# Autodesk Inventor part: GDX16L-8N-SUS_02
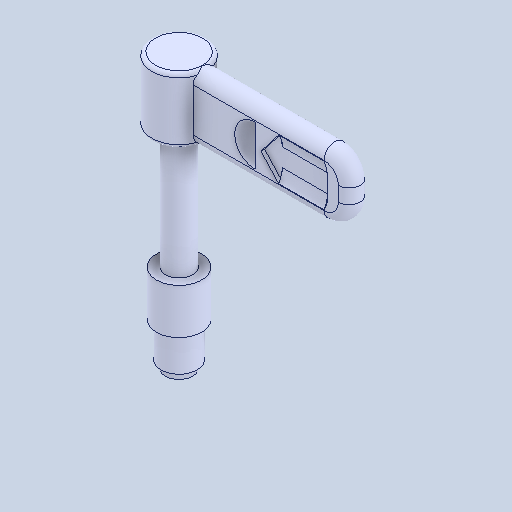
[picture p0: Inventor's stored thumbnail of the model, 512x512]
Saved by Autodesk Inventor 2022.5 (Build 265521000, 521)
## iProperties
Created: 2024-06
Part Number: GDX16L-8N-SUS_02
Material: 一般
Document SubType Name: Modeling
Designer: ImaoCorp
Density: 1 g/cm^3
Appearance: 既定
Author: ImaoCorp
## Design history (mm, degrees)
feature "GDX16L-8N-SUS_02"
node "ソリッド1"
